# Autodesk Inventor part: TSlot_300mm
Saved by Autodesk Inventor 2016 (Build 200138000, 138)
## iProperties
Created: 2016-03
Part Number: TSlot_300mm
Material: Generic
Document SubType Name: Modeling
Designer: bongo_000
Density: 1 g/cm^3
Appearance: Default
Author: bongo_000
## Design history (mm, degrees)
feature "SOLID1"
body "Solid1"
